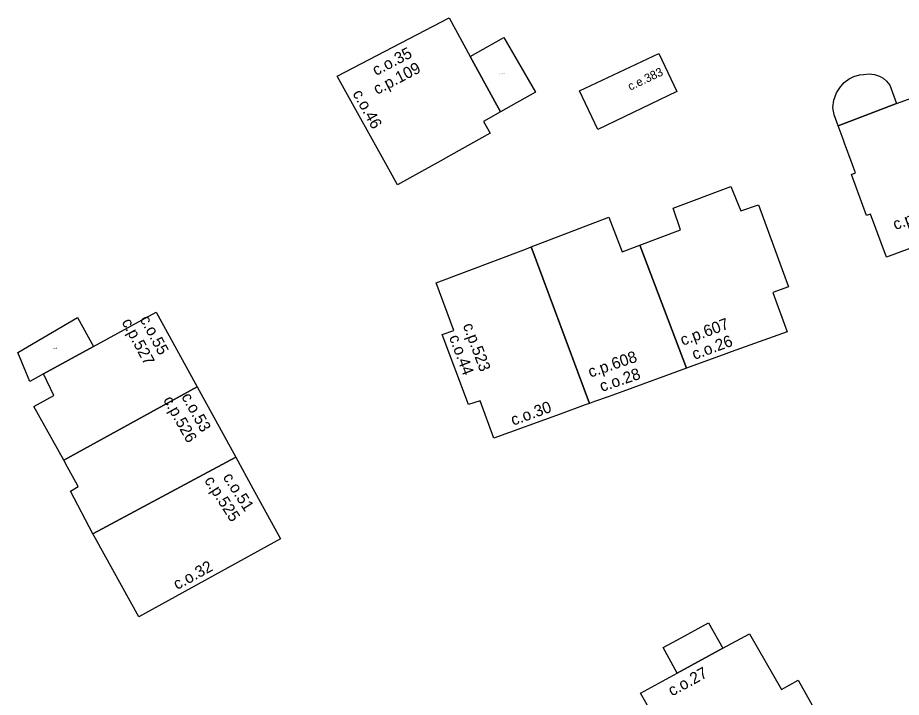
# Model space of a CAD drawing. Extents: x -600391 to -599491, y -1160176 to -1159402.
# Drawn here: x -600373.9 to -600297.1, y -1159718.1 to -1159659 of the extents above; entities that cross this region are included whole.
import ezdxf

# ---------------------------------------------------------------- set-up
doc = ezdxf.new("R2010")
doc.units = 0
for name, color, linetype in [('Level 10', 7, 'Continuous'), ('Level 12', 7, 'Continuous'), ('Level 23', 7, 'Continuous'), ('Level 24', 7, 'Continuous'), ('Level 61', 7, 'Continuous'), ('Level 62', 7, 'Continuous')]:
    doc.layers.add(name, color=color, linetype=linetype)

msp = doc.modelspace()

# ---------------------------------------------------------------- linework, layer by layer
at = {"layer": 'Level 61'}
for points in [[(-600346.12, -1159664.09), (-600336.38, -1159659.02)], [(-600346.12, -1159664.09), (-600336.38, -1159659.02)], [(-600336.38, -1159659.02), (-600334.54, -1159662.4)], [(-600336.38, -1159659.02), (-600334.54, -1159662.4)], [(-600334.54, -1159662.4), (-600331.63, -1159660.75)], [(-600331.63, -1159660.75), (-600328.87, -1159665.49)], [(-600334.54, -1159662.4), (-600331.92, -1159667.21)], [(-600331.92, -1159667.21), (-600334.54, -1159662.4)], [(-600334.54, -1159662.4), (-600331.92, -1159667.21)], [(-600325.03, -1159665.39), (-600318.15, -1159662.12)], [(-600318.15, -1159662.12), (-600316.58, -1159665.44)], [(-600301.17, -1159664.13), (-600300.7, -1159664)], [(-600300.7, -1159664), (-600300.33, -1159663.95)], [(-600300.33, -1159663.95), (-600299.85, -1159663.9)], [(-600299.85, -1159663.9), (-600299.38, -1159663.96)], [(-600299.38, -1159663.96), (-600298.96, -1159664.11)], [(-600345.94, -1159664.42), (-600346.12, -1159664.09)], [(-600345.94, -1159664.42), (-600346.12, -1159664.09)], [(-600341.63, -1159672.19), (-600345.94, -1159664.42)], [(-600341.63, -1159672.19), (-600345.94, -1159664.42)], [(-600302.35, -1159665.04), (-600302.01, -1159664.66)], [(-600302.01, -1159664.66), (-600301.6, -1159664.34)], [(-600301.6, -1159664.34), (-600301.46, -1159664.27)], [(-600301.46, -1159664.27), (-600301.17, -1159664.13)], [(-600298.96, -1159664.11), (-600298.64, -1159664.29)], [(-600298.64, -1159664.29), (-600298.35, -1159664.53)], [(-600298.35, -1159664.53), (-600298.05, -1159664.88)], [(-600328.87, -1159665.49), (-600331.92, -1159667.21)], [(-600323.46, -1159668.73), (-600325.03, -1159665.39)], [(-600316.58, -1159665.44), (-600323.46, -1159668.73)], [(-600302.69, -1159665.56), (-600302.35, -1159665.04)], [(-600298.05, -1159664.88), (-600297.47, -1159666.49)], [(-600303, -1159666.84), (-600302.92, -1159666.2)], [(-600302.92, -1159666.2), (-600302.69, -1159665.56)], [(-600297.47, -1159666.49), (-600295.07, -1159665.6)], [(-600302.88, -1159667.47), (-600303, -1159666.84)], [(-600297.47, -1159666.49), (-600302.54, -1159668.41)], [(-600302.54, -1159668.41), (-600297.47, -1159666.49)], [(-600331.92, -1159667.21), (-600333.39, -1159668.04)], [(-600331.92, -1159667.21), (-600333.39, -1159668.04)], [(-600302.54, -1159668.41), (-600302.88, -1159667.47)], [(-600333.39, -1159668.04), (-600332.8, -1159669.06)], [(-600333.39, -1159668.04), (-600332.8, -1159669.06)], [(-600302.11, -1159669.59), (-600302.54, -1159668.41)], [(-600332.8, -1159669.06), (-600336.24, -1159670.98)], [(-600332.8, -1159669.06), (-600336.24, -1159670.98)], [(-600301.99, -1159669.93), (-600302.11, -1159669.59)], [(-600301.33, -1159671.72), (-600301.99, -1159669.93)], [(-600337.11, -1159671.46), (-600339.03, -1159672.53)], [(-600337.11, -1159671.46), (-600339.03, -1159672.53)], [(-600336.24, -1159670.98), (-600337.11, -1159671.46)], [(-600336.24, -1159670.98), (-600337.11, -1159671.46)], [(-600340.87, -1159673.56), (-600341.63, -1159672.19)], [(-600340.87, -1159673.56), (-600341.63, -1159672.19)], [(-600301.21, -1159672.04), (-600301.33, -1159671.72)], [(-600301.04, -1159672.5), (-600301.21, -1159672.04)], [(-600339.03, -1159672.53), (-600340.87, -1159673.56)], [(-600339.03, -1159672.53), (-600340.87, -1159673.56)], [(-600301.38, -1159672.64), (-600301.04, -1159672.5)], [(-600300.08, -1159676.22), (-600301.38, -1159672.64)], [(-600316.89, -1159675.58), (-600311.87, -1159673.7)], [(-600311.87, -1159673.7), (-600311.02, -1159675.81)], [(-600311.02, -1159675.81), (-600309.47, -1159675.3)], [(-600309.47, -1159675.3), (-600306.86, -1159682.41)], [(-600285.93, -1159675.22), (-600298.35, -1159679.84)], [(-600316.27, -1159677.47), (-600316.89, -1159675.58)], [(-600299.72, -1159676.09), (-600300.08, -1159676.22)], [(-600298.35, -1159679.84), (-600299.72, -1159676.09)], [(-600329.25, -1159678.95), (-600322.5, -1159676.36)], [(-600322.5, -1159676.36), (-600321.34, -1159679.37)], [(-600319.78, -1159678.79), (-600316.27, -1159677.47)], [(-600337.51, -1159682.08), (-600329.64, -1159679.1)], [(-600329.64, -1159679.1), (-600329.25, -1159678.95)], [(-600324.17, -1159692.55), (-600329.25, -1159678.95)], [(-600329.25, -1159678.95), (-600324.17, -1159692.55)], [(-600321.34, -1159679.37), (-600319.78, -1159678.79)], [(-600315.75, -1159689.5), (-600319.78, -1159678.79)], [(-600319.78, -1159678.79), (-600315.75, -1159689.5)], [(-600335.96, -1159686.22), (-600337.51, -1159682.08)], [(-600306.86, -1159682.41), (-600308.22, -1159682.91)], [(-600308.22, -1159682.91), (-600306.99, -1159686.32)], [(-600367.31, -1159687.61), (-600361.85, -1159684.63)], [(-600361.85, -1159684.63), (-600358.29, -1159691.12)], [(-600373.9, -1159688.12), (-600368.7, -1159685.07)], [(-600373.9, -1159688.12), (-600368.7, -1159685.07)], [(-600368.7, -1159685.07), (-600367.31, -1159687.61)], [(-600368.7, -1159685.07), (-600367.31, -1159687.61)], [(-600336.97, -1159686.56), (-600335.96, -1159686.22)], [(-600334.69, -1159692.64), (-600336.97, -1159686.56)], [(-600307.39, -1159686.47), (-600311.84, -1159688.08)], [(-600306.99, -1159686.32), (-600307.39, -1159686.47)], [(-600371.66, -1159689.99), (-600367.31, -1159687.61)], [(-600367.31, -1159687.61), (-600371.66, -1159689.99)], [(-600367.31, -1159687.61), (-600371.66, -1159689.99)], [(-600372.85, -1159690.64), (-600373.9, -1159688.12)], [(-600372.85, -1159690.64), (-600373.9, -1159688.12)], [(-600312.31, -1159688.25), (-600315.75, -1159689.5)], [(-600311.84, -1159688.08), (-600312.31, -1159688.25)], [(-600371.66, -1159689.99), (-600372.85, -1159690.64)], [(-600371.66, -1159689.99), (-600372.85, -1159690.64)], [(-600370.75, -1159691.85), (-600371.66, -1159689.99)], [(-600315.75, -1159689.5), (-600321.28, -1159691.51)], [(-600358.29, -1159691.12), (-600369.9, -1159697.48)], [(-600369.9, -1159697.48), (-600358.29, -1159691.12)], [(-600358.29, -1159691.12), (-600354.94, -1159697.22)], [(-600321.28, -1159691.51), (-600322.56, -1159691.97)], [(-600372.49, -1159692.83), (-600370.75, -1159691.85)], [(-600333.67, -1159692.32), (-600334.69, -1159692.64)], [(-600332.48, -1159695.57), (-600333.67, -1159692.32)], [(-600323.73, -1159692.39), (-600324.17, -1159692.55)], [(-600322.56, -1159691.97), (-600323.73, -1159692.39)], [(-600369.9, -1159697.48), (-600372.49, -1159692.83)], [(-600324.54, -1159692.68), (-600326.73, -1159693.48)], [(-600324.17, -1159692.55), (-600324.54, -1159692.68)], [(-600326.73, -1159693.48), (-600332.48, -1159695.57)], [(-600369.57, -1159698.08), (-600369.9, -1159697.48)], [(-600367.36, -1159703.88), (-600354.94, -1159697.22)], [(-600354.94, -1159697.22), (-600367.36, -1159703.88)], [(-600354.94, -1159697.22), (-600353.45, -1159699.94)], [(-600368.84, -1159699.39), (-600369.57, -1159698.08)], [(-600369.32, -1159700.19), (-600368.63, -1159699.77)], [(-600368.63, -1159699.77), (-600368.84, -1159699.39)], [(-600353.45, -1159699.94), (-600351.04, -1159704.32)], [(-600367.36, -1159703.88), (-600369.32, -1159700.19)], [(-600367.14, -1159704.28), (-600367.36, -1159703.88)], [(-600363.37, -1159711.1), (-600367.14, -1159704.28)], [(-600351.04, -1159704.32), (-600363.37, -1159711.1)], [(-600316.53, -1159713.1), (-600313.81, -1159711.62)], [(-600313.81, -1159711.62), (-600312.59, -1159713.84)], [(-600317.76, -1159713.77), (-600316.53, -1159713.1)], [(-600312.59, -1159713.84), (-600310.26, -1159712.57)], [(-600310.26, -1159712.57), (-600307.47, -1159717.43)], [(-600316.55, -1159716), (-600317.76, -1159713.77)], [(-600316.55, -1159716), (-600312.59, -1159713.84)], [(-600312.59, -1159713.84), (-600316.55, -1159716)], [(-600319.73, -1159717.73), (-600316.55, -1159716)], [(-600307.47, -1159717.43), (-600306.02, -1159716.62)], [(-600306.02, -1159716.62), (-600304.28, -1159719.7)], [(-600314.98, -1159726.08), (-600319.73, -1159717.73)]]:
    msp.add_lwpolyline(points, dxfattribs=at)
at = {"layer": 'Level 62'}
for points in [[(-600345.94, -1159664.42), (-600346.12, -1159664.09), (-600336.38, -1159659.02), (-600334.54, -1159662.4), (-600331.92, -1159667.21), (-600333.39, -1159668.04), (-600332.8, -1159669.06), (-600336.24, -1159670.98), (-600337.11, -1159671.46), (-600339.03, -1159672.53), (-600340.87, -1159673.56), (-600341.63, -1159672.19), (-600345.94, -1159664.42)], [(-600345.94, -1159664.42), (-600346.12, -1159664.09), (-600336.38, -1159659.02), (-600334.54, -1159662.4), (-600331.92, -1159667.21), (-600333.39, -1159668.04), (-600332.8, -1159669.06), (-600336.24, -1159670.98), (-600337.11, -1159671.46), (-600339.03, -1159672.53), (-600340.87, -1159673.56), (-600341.63, -1159672.19), (-600345.94, -1159664.42)], [(-600334.54, -1159662.4), (-600331.63, -1159660.75), (-600328.87, -1159665.49), (-600331.92, -1159667.21), (-600334.54, -1159662.4)], [(-600318.15, -1159662.12), (-600316.58, -1159665.44), (-600323.46, -1159668.73), (-600325.03, -1159665.39), (-600318.15, -1159662.12)], [(-600298.05, -1159664.88), (-600297.47, -1159666.49), (-600302.54, -1159668.41), (-600302.88, -1159667.47), (-600303, -1159666.84), (-600302.92, -1159666.2), (-600302.69, -1159665.56), (-600302.35, -1159665.04), (-600302.01, -1159664.66), (-600301.6, -1159664.34), (-600301.46, -1159664.27), (-600301.17, -1159664.13), (-600300.7, -1159664), (-600300.33, -1159663.95), (-600299.85, -1159663.9), (-600299.38, -1159663.96), (-600298.96, -1159664.11), (-600298.64, -1159664.29), (-600298.35, -1159664.53), (-600298.05, -1159664.88)], [(-600301.33, -1159671.72), (-600301.99, -1159669.93), (-600302.11, -1159669.59), (-600302.54, -1159668.41), (-600297.47, -1159666.49), (-600295.07, -1159665.6), (-600290.21, -1159663.81), (-600288.63, -1159667.85), (-600288.34, -1159667.77), (-600286.92, -1159671.6), (-600287.29, -1159671.79), (-600285.93, -1159675.22), (-600298.35, -1159679.84), (-600299.72, -1159676.09), (-600300.08, -1159676.22), (-600301.38, -1159672.64), (-600301.04, -1159672.5), (-600301.21, -1159672.04), (-600301.33, -1159671.72)], [(-600306.86, -1159682.41), (-600308.22, -1159682.91), (-600306.99, -1159686.32), (-600307.39, -1159686.47), (-600311.84, -1159688.08), (-600312.31, -1159688.25), (-600315.75, -1159689.5), (-600319.78, -1159678.79), (-600316.27, -1159677.47), (-600316.89, -1159675.58), (-600311.87, -1159673.7), (-600311.02, -1159675.81), (-600309.47, -1159675.3), (-600306.86, -1159682.41)], [(-600315.75, -1159689.5), (-600321.28, -1159691.51), (-600322.56, -1159691.97), (-600323.73, -1159692.39), (-600324.17, -1159692.55), (-600329.25, -1159678.95), (-600322.5, -1159676.36), (-600321.34, -1159679.37), (-600319.78, -1159678.79), (-600315.75, -1159689.5)], [(-600324.17, -1159692.55), (-600324.54, -1159692.68), (-600326.73, -1159693.48), (-600332.48, -1159695.57), (-600333.67, -1159692.32), (-600334.69, -1159692.64), (-600336.97, -1159686.56), (-600335.96, -1159686.22), (-600337.51, -1159682.08), (-600329.64, -1159679.1), (-600329.25, -1159678.95), (-600324.17, -1159692.55)], [(-600367.31, -1159687.61), (-600361.85, -1159684.63), (-600358.29, -1159691.12), (-600369.9, -1159697.48), (-600372.49, -1159692.83), (-600370.75, -1159691.85), (-600371.66, -1159689.99), (-600367.31, -1159687.61)], [(-600367.31, -1159687.61), (-600371.66, -1159689.99), (-600372.85, -1159690.64), (-600373.9, -1159688.12), (-600368.7, -1159685.07), (-600367.31, -1159687.61)], [(-600367.31, -1159687.61), (-600371.66, -1159689.99), (-600372.85, -1159690.64), (-600373.9, -1159688.12), (-600368.7, -1159685.07), (-600367.31, -1159687.61)], [(-600358.29, -1159691.12), (-600354.94, -1159697.22), (-600367.36, -1159703.88), (-600369.32, -1159700.19), (-600368.63, -1159699.77), (-600368.84, -1159699.39), (-600369.57, -1159698.08), (-600369.9, -1159697.48), (-600358.29, -1159691.12)], [(-600363.37, -1159711.1), (-600367.14, -1159704.28), (-600367.36, -1159703.88), (-600354.94, -1159697.22), (-600353.45, -1159699.94), (-600351.04, -1159704.32), (-600363.37, -1159711.1)], [(-600316.55, -1159716), (-600317.76, -1159713.77), (-600316.53, -1159713.1), (-600313.81, -1159711.62), (-600312.59, -1159713.84), (-600316.55, -1159716)], [(-600305.98, -1159721.16), (-600314.98, -1159726.08), (-600319.73, -1159717.73), (-600316.55, -1159716), (-600312.59, -1159713.84), (-600310.26, -1159712.57), (-600307.47, -1159717.43), (-600306.02, -1159716.62), (-600304.28, -1159719.7), (-600304.03, -1159720.11), (-600305.98, -1159721.16)]]:
    msp.add_lwpolyline(points, dxfattribs=at)

# ---------------------------------------------------------------- texts
at = {"layer": 'Level 10'}
for s, rotation, p in [('c.o.35', 27.47219, (-600342.737, -1159664.094)), ('c.o.46', 299.18984, (-600344.806, -1159665.608)), ('c.o.55', 298.12574, (-600363.301, -1159685.228)), ('c.o.44', 290.55537, (-600336.407, -1159686.793)), ('c.o.26', 20.34145, (-600315.041, -1159688.776)), ('c.o.28', 18.9296, (-600323.094, -1159691.561)), ('c.o.53', 299.413, (-600359.693, -1159691.965)), ('c.o.30', 19.90087, (-600330.808, -1159694.495)), ('c.o.51', 302.77791, (-600356.096, -1159698.968)), ('c.o.32', 28.70009, (-600360.032, -1159708.781)), ('c.o.27', 28.58714, (-600317.002, -1159718.031))]:
    msp.add_text(s, height=1, rotation=rotation, dxfattribs=at).set_placement(p)
at = {"layer": 'Level 12'}
for s, rotation, p in [('c.p.109', 27.47219, (-600342.648, -1159665.737)), ('c.p.605', 20.40114, (-600297.568, -1159677.493)), ('c.p.527', 298.12574, (-600364.88, -1159685.473)), ('c.p.607', 20.34145, (-600316.059, -1159687.55)), ('c.p.523', 290.55537, (-600335.201, -1159685.767)), ('c.p.608', 18.9296, (-600324.095, -1159690.318)), ('c.p.526', 299.413, (-600361.275, -1159692.248)), ('c.p.525', 302.77791, (-600357.703, -1159699.249))]:
    msp.add_text(s, height=1, rotation=rotation, dxfattribs=at).set_placement(p)
at = {"layer": 'Level 23'}
msp.add_text('c.e.383', height=0.74, rotation=25.4213, dxfattribs=at).set_placement((-600320.629, -1159665.377))
at = {"layer": 'Level 24'}
for s, p in [('c.z.323', (-600331.979, -1159663.957)), ('c.z.317', (-600370.829, -1159687.807))]:
    msp.add_text(s, height=0.1, dxfattribs=at).set_placement(p)

doc.saveas('drawing.dxf')
